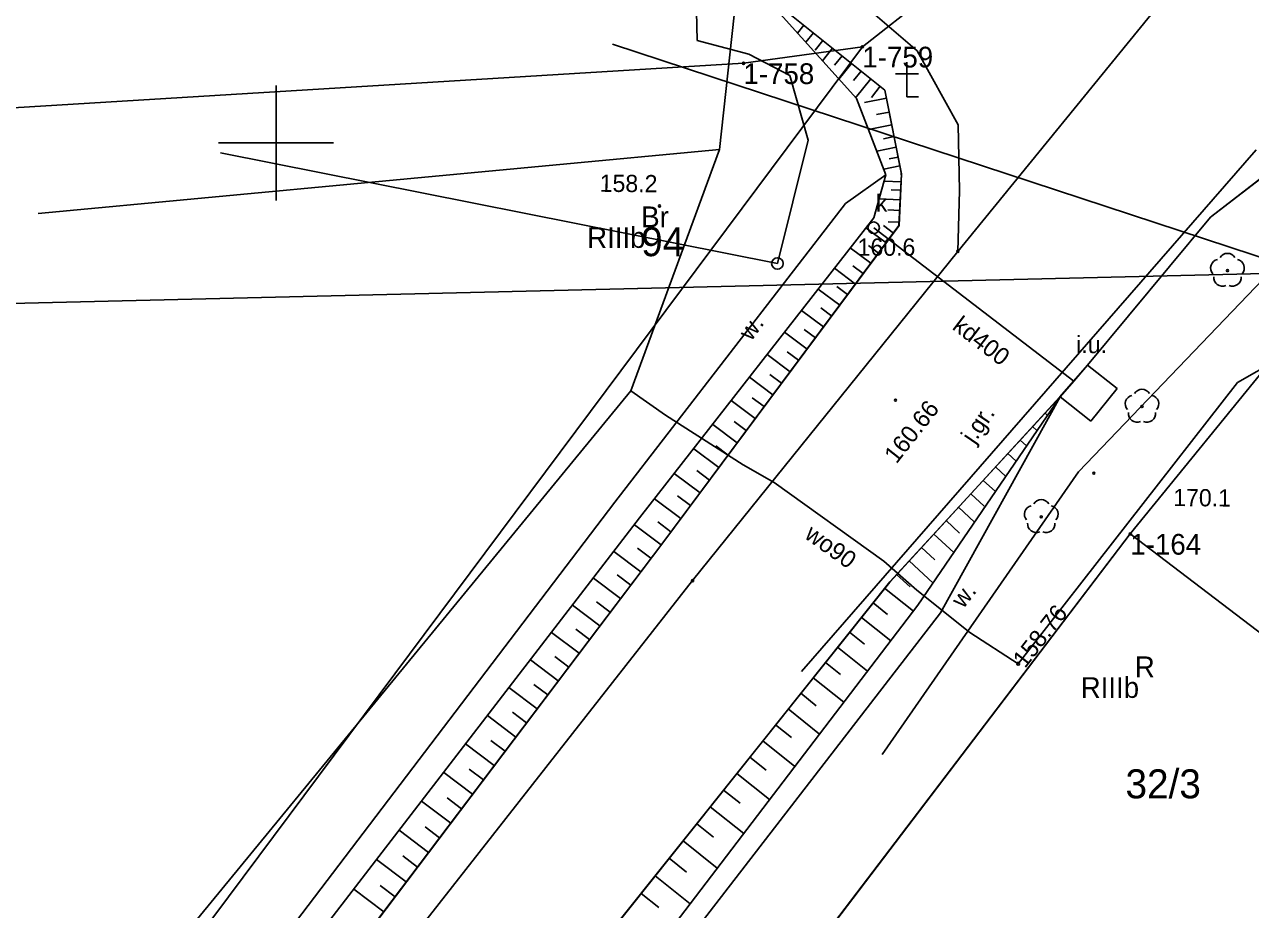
# Model space of a CAD drawing. Extents: x 5598798 to 5599616, y 5661498 to 5662453.
# Drawn here: x 5599039.1 to 5599092.4, y 5661566.7 to 5661605.1 of the extents above; entities that cross this region are included whole.
import ezdxf

# ---------------------------------------------------------------- set-up
doc = ezdxf.new("R2010")
doc.units = 0
for name, color, linetype in [('BUBZ_L_1', 7, 'Continuous'), ('Dzialki', 7, 'Continuous'), ('Kontury', 7, 'Continuous'), ('KTJZ_E_T_0', 7, 'Continuous'), ('KTJZ_L_0', 7, 'Continuous'), ('Numery_dzialek', 7, 'Continuous'), ('Numery_konturow', 7, 'Continuous'), ('Numery_punktow', 7, 'Continuous'), ('Numery_uzytkow', 7, 'Continuous'), ('OBOO_T_0', 7, 'Continuous'), ('OBOP_T_1', 7, 'Continuous'), ('Podzial_sekcyjny_krzyze', 7, 'Continuous'), ('PTRW_E_T_0', 7, 'Continuous'), ('PTRW_L_1', 7, 'Continuous'), ('Punkty', 7, 'Continuous'), ('RTPW_T_0', 7, 'Continuous'), ('RTPW_T_1', 7, 'Continuous'), ('SUOW_L_0', 7, 'Continuous'), ('SUPE_L_3', 7, 'Continuous'), ('SUPK_E_T_0', 7, 'Continuous'), ('SUPK_L_0', 7, 'Continuous'), ('SUPT_L_0', 7, 'Continuous'), ('SUPW_E_T_0', 7, 'Continuous'), ('SUPW_L_0', 7, 'Continuous'), ('SUSM_T_3', 7, 'Continuous'), ('SUTW_T_0', 7, 'Continuous'), ('SUUK_E_T_8', 7, 'Continuous'), ('SUUK_E_T_9', 7, 'Continuous'), ('SUUK_L_8', 7, 'Continuous'), ('SUUK_T_2', 7, 'Continuous'), ('Uzytki', 7, 'Continuous')]:
    doc.layers.add(name, color=color, linetype=linetype)

# ---------------------------------------------------------------- blocks, each defined once
blk = doc.blocks.new('GRO')
blk.add_circle((0, 0), 0.045)
blk = doc.blocks.new('2_OBOO01_01')
for p, q in [((0, 1.5), (0, 0)), ((-0.5, 1), (0.5, 1)), ((0, 0), (0.5, 0))]:
    blk.add_line(p, q)
blk = doc.blocks.new('2_OBOP02_01')
blk.add_circle((0, 0), 0.045)
for centre, start, end in [((0, 0.375056), 30.140124, 149.859876), ((-0.356659, 0.115892), 102.144465, 221.860023), ((0.356659, 0.115892), 318.139977, 77.855535), ((-0.220404, -0.303384), 174.148182, 293.854228), ((0.220404, -0.303384), 246.145772, 5.851818)]:
    blk.add_arc(centre, 0.375, start, end)
blk = doc.blocks.new('2_RTPW01')
blk.add_circle((0, 0), 0.045)
blk = doc.blocks.new('2_RTPW02')
blk.add_circle((0, 0), 0.045)
blk = doc.blocks.new('4_SUSM04_01')
blk.add_circle((0, 0), 0.25)
blk = doc.blocks.new('4_SUPS01_08')
blk.add_circle((0, 0), 0.0625)
blk = doc.blocks.new('4_SUUS15_05')
blk.add_circle((0, 0), 0.25)

msp = doc.modelspace()

# ---------------------------------------------------------------- linework, layer by layer
at = {"layer": 'BUBZ_L_1'}
for p, q in [((5599070.866619, 5661606.777722), (5599075.229063, 5661601.930102)), ((5599076.471074, 5661602.299748), (5599070.866619, 5661606.777722)), ((5599072.944885, 5661605.117182), (5599072.670266, 5661604.77348)), ((5599073.360538, 5661604.785074), (5599073.030995, 5661604.372631)), ((5599073.776191, 5661604.452966), (5599073.444083, 5661604.037313)), ((5599074.191844, 5661604.120859), (5599073.752454, 5661603.570934)), ((5599074.607497, 5661603.788751), (5599074.275389, 5661603.373097)), ((5599075.023151, 5661603.456643), (5599074.473912, 5661602.769238)), ((5599075.438804, 5661603.124535), (5599075.106696, 5661602.708881)), ((5599075.854457, 5661602.792427), (5599075.195371, 5661601.967541)), ((5599076.27011, 5661602.460319), (5599075.885608, 5661601.979091)), ((5599075.229063, 5661601.930102), (5599076.512086, 5661598.615971)), ((5599076.540369, 5661601.947766), (5599075.579508, 5661601.758599)), ((5599077.18899, 5661598.653147), (5599076.471074, 5661602.299748)), ((5599076.659354, 5661601.343395), (5599076.100379, 5661601.233348)), ((5599076.7694, 5661600.784421), (5599075.750273, 5661600.583782)), ((5599076.86972, 5661600.274857), (5599076.405199, 5661600.183406)), ((5599076.961171, 5661599.810336), (5599076.114252, 5661599.643601)), ((5599077.044539, 5661599.386877), (5599076.658511, 5661599.310878)), ((5599077.120537, 5661599.000849), (5599076.416727, 5661598.862288)), ((5599077.08532, 5661596.411278), (5599077.18899, 5661598.653147)), ((5599076.512086, 5661598.615971), (5599075.983367, 5661596.742132)), ((5599077.173142, 5661598.310425), (5599076.435498, 5661598.344535)), ((5599077.188792, 5661598.648868), (5599077.153389, 5661598.650505)), ((5599077.156086, 5661597.941603), (5599076.744319, 5661597.960644)), ((5599077.137045, 5661597.529836), (5599076.217621, 5661597.572353)), ((5599077.115787, 5661597.070124), (5599076.602546, 5661597.093857)), ((5599075.983367, 5661596.742132), (5599065.807304, 5661583.70311)), ((5599077.092053, 5661596.556883), (5599076.616602, 5661596.578869)), ((5599066.813154, 5661582.630911), (5599077.08532, 5661596.411278)), ((5599076.519789, 5661595.652604), (5599075.643087, 5661596.306116)), ((5599076.842968, 5661596.086157), (5599076.409415, 5661596.409336)), ((5599076.193033, 5661595.214254), (5599075.749831, 5661595.544626)), ((5599075.862661, 5661594.771051), (5599074.966447, 5661595.439108)), ((5599075.190908, 5661593.869877), (5599074.274746, 5661594.552803)), ((5599075.528633, 5661594.322944), (5599075.075566, 5661594.660669)), ((5599074.504203, 5661592.948646), (5599073.56765, 5661593.646771)), ((5599074.849445, 5661593.411796), (5599074.386294, 5661593.757038)), ((5599074.15514, 5661592.48037), (5599073.681682, 5661592.833295)), ((5599073.802215, 5661592.006911), (5599072.844817, 5661592.720574)), ((5599073.084602, 5661591.044215), (5599072.105896, 5661591.773763)), ((5599073.445383, 5661591.528212), (5599072.961386, 5661591.888993)), ((5599072.351017, 5661590.060093), (5599071.350528, 5661590.805878)), ((5599072.719828, 5661590.554862), (5599072.225059, 5661590.923673)), ((5599071.601105, 5661589.054068), (5599070.578348, 5661589.816452)), ((5599071.978125, 5661589.559849), (5599071.472344, 5661589.936868)), ((5599070.834503, 5661588.025651), (5599069.788982, 5661588.805003)), ((5599071.219913, 5661588.542689), (5599070.702875, 5661588.9281)), ((5599084.083213, 5661588.966374), (5599076.678362, 5661580.924495)), ((5599077.9025, 5661579.911014), (5599084.083213, 5661588.966374)), ((5599083.9679, 5661588.841141), (5599083.986221, 5661588.824271)), ((5599083.430397, 5661588.257398), (5599083.534117, 5661588.161894)), ((5599070.050838, 5661586.974345), (5599068.982047, 5661587.771043)), ((5599070.444826, 5661587.502891), (5599069.916281, 5661587.896879)), ((5599082.892895, 5661587.673654), (5599083.082013, 5661587.499517)), ((5599082.355392, 5661587.089911), (5599082.629909, 5661586.837139)), ((5599069.249731, 5661585.89964), (5599068.157152, 5661586.71407)), ((5599069.652488, 5661586.439949), (5599069.112179, 5661586.842707)), ((5599081.817889, 5661586.506168), (5599082.177805, 5661586.174762)), ((5599081.280386, 5661585.922424), (5599081.725701, 5661585.512385)), ((5599068.430793, 5661584.801015), (5599067.313897, 5661585.633572)), ((5599068.842515, 5661585.35335), (5599068.29018, 5661585.765072)), ((5599080.742884, 5661585.338681), (5599081.273597, 5661584.850007)), ((5599067.593629, 5661583.677938), (5599066.451874, 5661584.529026)), ((5599068.014515, 5661584.242567), (5599067.449886, 5661584.663452)), ((5599080.205381, 5661584.754938), (5599080.789124, 5661584.217435)), ((5599079.667878, 5661584.171194), (5599080.369389, 5661583.525253)), ((5599065.807304, 5661583.70311), (5599042.195012, 5661553.064547)), ((5599066.737121, 5661582.530399), (5599065.578805, 5661583.406618)), ((5599067.168085, 5661583.107061), (5599066.59089, 5661583.537314)), ((5599079.130375, 5661583.587451), (5599079.714119, 5661583.049948)), ((5599078.592872, 5661583.003708), (5599079.465181, 5661582.200498)), ((5599043.59456, 5661551.937133), (5599066.813154, 5661582.630911)), ((5599065.858935, 5661581.369484), (5599064.690196, 5661582.253587)), ((5599066.299011, 5661581.951242), (5599065.717254, 5661582.391318)), ((5599078.05537, 5661582.419964), (5599078.639113, 5661581.882462)), ((5599077.517867, 5661581.836221), (5599078.560973, 5661580.875743)), ((5599064.972847, 5661580.198121), (5599063.793591, 5661581.090181)), ((5599065.416884, 5661580.785114), (5599064.829891, 5661581.22915)), ((5599076.980364, 5661581.252478), (5599077.564108, 5661580.714975)), ((5599076.678362, 5661580.924495), (5599063.229428, 5661564.085129)), ((5599076.458557, 5661580.649278), (5599077.70574, 5661579.653203)), ((5599064.526818, 5661579.608493), (5599063.934543, 5661580.056525)), ((5599075.954972, 5661580.01874), (5599076.58551, 5661579.515154)), ((5599064.078786, 5661579.016218), (5599062.888918, 5661579.916305)), ((5599066.809784, 5661565.376446), (5599077.9025, 5661579.911014)), ((5599075.445776, 5661579.381178), (5599076.7209, 5661578.362787)), ((5599063.176679, 5661577.823679), (5599061.976103, 5661578.731866)), ((5599063.628742, 5661578.421284), (5599063.031137, 5661578.873348)), ((5599074.930908, 5661578.736513), (5599075.575573, 5661578.221646)), ((5599074.410305, 5661578.084668), (5599075.713996, 5661577.043461)), ((5599062.266454, 5661576.620409), (5599061.055074, 5661577.536768)), ((5599062.722585, 5661577.223392), (5599062.119603, 5661577.679523)), ((5599073.883902, 5661577.42556), (5599074.543009, 5661576.899157)), ((5599061.348038, 5661575.406311), (5599060.125758, 5661576.330916)), ((5599061.808274, 5661576.014719), (5599061.199865, 5661576.474956)), ((5599073.351635, 5661576.759111), (5599074.684534, 5661575.694577)), ((5599072.813438, 5661576.085237), (5599073.487312, 5661575.54704)), ((5599060.885735, 5661574.795171), (5599060.271851, 5661575.259549)), ((5599072.269247, 5661575.403856), (5599073.632008, 5661574.315472)), ((5599060.421357, 5661574.181287), (5599059.188078, 5661575.114213)), ((5599071.718993, 5661574.714885), (5599072.407964, 5661574.164631)), ((5599059.486338, 5661572.94524), (5599058.241961, 5661573.88656)), ((5599059.954894, 5661573.564648), (5599059.335487, 5661574.033204)), ((5599071.162609, 5661574.018238), (5599072.555901, 5661572.905471)), ((5599070.600027, 5661573.313832), (5599071.304434, 5661572.75125)), ((5599058.542904, 5661571.69807), (5599057.287329, 5661572.647861)), ((5599059.015677, 5661572.323051), (5599058.390696, 5661572.795824)), ((5599070.031178, 5661572.601578), (5599071.455686, 5661571.46388)), ((5599058.068008, 5661571.070282), (5599057.437403, 5661571.54731)), ((5599069.455992, 5661571.881389), (5599070.176181, 5661571.306204)), ((5599057.590981, 5661570.439676), (5599056.324107, 5661571.398015)), ((5599068.874399, 5661571.153178), (5599070.330821, 5661569.989992)), ((5599068.286327, 5661570.416855), (5599069.02265, 5661569.828783)), ((5599056.630491, 5661569.169959), (5599055.352218, 5661570.136921)), ((5599057.111812, 5661569.806239), (5599056.475531, 5661570.28756)), ((5599067.691704, 5661569.672329), (5599069.180755, 5661568.483083)), ((5599055.661359, 5661567.888816), (5599054.371582, 5661568.864479)), ((5599056.14701, 5661568.530822), (5599055.505004, 5661569.016474)), ((5599067.090456, 5661568.91951), (5599067.843276, 5661568.318262)), ((5599066.482511, 5661568.158304), (5599068.004923, 5661566.942414)), ((5599054.683505, 5661566.596144), (5599053.382122, 5661567.580587)), ((5599055.173527, 5661567.243927), (5599054.525743, 5661567.733949)), ((5599065.867794, 5661567.388618), (5599066.63748, 5661566.7739))]:
    msp.add_line(p, q, dxfattribs=at)
at = {"layer": 'Dzialki'}
for p, q in [((5599075.49, 5661604.18), (5599100.76, 5661624.05)), ((5599087.14, 5661583.01), (5599113.12, 5661614.97)), ((5599040.18, 5661556.86), (5599075.49, 5661604.18)), ((5599075.49, 5661604.18), (5599070.32, 5661603.46)), ((5599070.32, 5661603.46), (5599030.46, 5661601.04)), ((5599087.14, 5661583.01), (5599072.29, 5661563.53)), ((5599107.79, 5661567.29), (5599087.14, 5661583.01))]:
    msp.add_line(p, q, dxfattribs=at)
at = {"layer": 'Kontury'}
for p, q in [((5599075.49, 5661604.18), (5599040.18, 5661556.86)), ((5599070.32, 5661603.46), (5599075.49, 5661604.18)), ((5599030.46, 5661601.04), (5599070.32, 5661603.46)), ((5599087.14, 5661583.01), (5599045.53, 5661528.41)), ((5599127.28, 5661552.45), (5599087.14, 5661583.01))]:
    msp.add_line(p, q, dxfattribs=at)
at = {"layer": 'KTJZ_L_0'}
for p, q in [((5599090.42, 5661608.51), (5599079.64, 5661595.29)), ((5599070.87, 5661606.78), (5599076.47, 5661602.3)), ((5599077.87, 5661604.01), (5599074.48, 5661606.91)), ((5599079.66, 5661600.79), (5599077.87, 5661604.01)), ((5599076.47, 5661602.3), (5599077.19, 5661598.65)), ((5599079.71, 5661597.94), (5599079.66, 5661600.79)), ((5599072.84, 5661577.03), (5599092.61, 5661599.7)), ((5599090.63, 5661596.78), (5599093.18, 5661598.74)), ((5599077.19, 5661598.65), (5599077.08, 5661596.41)), ((5599079.64, 5661595.29), (5599079.71, 5661597.94)), ((5599085.28, 5661590.34), (5599090.63, 5661596.78)), ((5599077.08, 5661596.41), (5599066.81, 5661582.63)), ((5599079.64, 5661595.29), (5599068.11, 5661580.98)), ((5599084.08, 5661588.97), (5599085.28, 5661590.34)), ((5599076.68, 5661580.92), (5599084.08, 5661588.97)), ((5599066.81, 5661582.63), (5599043.59, 5661551.94)), ((5599068.11, 5661580.98), (5599036.03, 5661540.16)), ((5599063.23, 5661564.09), (5599076.68, 5661580.92))]:
    msp.add_line(p, q, dxfattribs=at)
at = {"layer": 'Podzial_sekcyjny_krzyze'}
for p, q in [((5599050, 5661597.5), (5599050, 5661602.5)), ((5599047.5, 5661600), (5599052.5, 5661600))]:
    msp.add_line(p, q, dxfattribs=at)
at = {"layer": 'PTRW_L_1'}
for p, q in [((5599090.626974, 5661596.782226), (5599093.183537, 5661598.743348)), ((5599074.75333, 5661597.367895), (5599076.512086, 5661598.615971)), ((5599076.512086, 5661598.615971), (5599075.983367, 5661596.742132)), ((5599064.730159, 5661584.391797), (5599074.75333, 5661597.367895)), ((5599075.983367, 5661596.742132), (5599065.807304, 5661583.70311)), ((5599090.626974, 5661596.782226), (5599085.282468, 5661590.344266)), ((5599094.36359, 5661595.600952), (5599084.881522, 5661585.712704)), ((5599085.282468, 5661590.344266), (5599084.083213, 5661588.966374)), ((5599084.083213, 5661588.966374), (5599078.884868, 5661579.576282)), ((5599084.881522, 5661585.712704), (5599076.349046, 5661573.424877)), ((5599041.326774, 5661553.647692), (5599064.730159, 5661584.391797)), ((5599065.807304, 5661583.70311), (5599042.195012, 5661553.064547)), ((5599060.855368, 5661556.243842), (5599078.884868, 5661579.576282))]:
    msp.add_line(p, q, dxfattribs=at)
at = {"layer": 'SUOW_L_0'}
msp.add_line((5599071.662016, 5661585.242449), (5599076.421794, 5661581.828971), dxfattribs=at)
msp.add_line((5599071.662016, 5661585.242449), (5599076.421794, 5661581.828971), dxfattribs=at)
at = {"layer": 'SUPE_L_3'}
for p, q in [((5599094.830509, 5661594.368063), (5599064.625935, 5661604.291571)), ((5598996.482621, 5661592.032784), (5599094.830509, 5661594.368063))]:
    msp.add_line(p, q, dxfattribs=at)
at = {"layer": 'SUPK_L_0'}
msp.add_line((5599075.98245, 5661596.315806), (5599084.68284, 5661589.65532), dxfattribs=at)
msp.add_line((5599075.98245, 5661596.315806), (5599084.68284, 5661589.65532), dxfattribs=at)
at = {"layer": 'SUPT_L_0'}
for p, q in [((5599068.113234, 5661613.285024), (5599068.303936, 5661604.455202)), ((5599068.303936, 5661604.455202), (5599070.5486, 5661603.855912)), ((5599070.5486, 5661603.855912), (5599072.330334, 5661602.935955)), ((5599072.330334, 5661602.935955), (5599073.134622, 5661600.122903)), ((5599073.134622, 5661600.122903), (5599071.795842, 5661594.759967)), ((5599071.795842, 5661594.759967), (5599047.577678, 5661599.576295))]:
    msp.add_line(p, q, dxfattribs=at)
at = {"layer": 'SUPW_L_0'}
for p, q in [((5599070.225874, 5661608.370705), (5599069.272086, 5661599.714965)), ((5599070.225874, 5661608.370705), (5599069.272086, 5661599.714965)), ((5599069.272086, 5661599.714965), (5599039.661276, 5661596.940988)), ((5599069.272086, 5661599.714965), (5599039.661276, 5661596.940988)), ((5599069.272086, 5661599.714965), (5599065.428445, 5661589.232718)), ((5599069.272086, 5661599.714965), (5599065.428445, 5661589.232718)), ((5599091.802605, 5661589.592031), (5599097.866615, 5661593.06142)), ((5599091.802605, 5661589.592031), (5599097.866615, 5661593.06142)), ((5599082.26584, 5661577.369633), (5599091.802605, 5661589.592031)), ((5599082.26584, 5661577.369633), (5599091.802605, 5661589.592031)), ((5599065.428445, 5661589.232718), (5599041.92742, 5661560.625386)), ((5599065.428445, 5661589.232718), (5599041.92742, 5661560.625386)), ((5599065.428445, 5661589.232718), (5599066.933375, 5661588.166403)), ((5599065.428445, 5661589.232718), (5599066.933375, 5661588.166403)), ((5599066.933375, 5661588.166403), (5599070.313898, 5661586.012186)), ((5599066.933375, 5661588.166403), (5599070.313898, 5661586.012186)), ((5599070.313898, 5661586.012186), (5599071.662016, 5661585.242449)), ((5599070.313898, 5661586.012186), (5599071.662016, 5661585.242449)), ((5599071.662016, 5661585.242449), (5599076.421794, 5661581.828971)), ((5599071.662016, 5661585.242449), (5599076.421794, 5661581.828971)), ((5599076.421794, 5661581.828971), (5599077.861045, 5661580.571075)), ((5599076.421794, 5661581.828971), (5599077.861045, 5661580.571075)), ((5599077.861045, 5661580.571075), (5599080.163893, 5661578.732524)), ((5599077.861045, 5661580.571075), (5599080.163893, 5661578.732524)), ((5599080.163893, 5661578.732524), (5599082.26584, 5661577.369633)), ((5599080.163893, 5661578.732524), (5599082.26584, 5661577.369633))]:
    msp.add_line(p, q, dxfattribs=at)
at = {"layer": 'SUUK_L_8'}
for p, q in [((5599084.68284, 5661589.65532), (5599085.282468, 5661590.344266)), ((5599085.282468, 5661590.344266), (5599086.566272, 5661589.32295)), ((5599084.083213, 5661588.966374), (5599084.68284, 5661589.65532)), ((5599086.566272, 5661589.32295), (5599085.417924, 5661587.906196)), ((5599085.417924, 5661587.906196), (5599084.083213, 5661588.966374))]:
    msp.add_line(p, q, dxfattribs=at)
at = {"layer": 'Uzytki'}
for p, q in [((5599040.18, 5661556.86), (5599075.49, 5661604.18)), ((5599075.49, 5661604.18), (5599070.32, 5661603.46)), ((5599070.32, 5661603.46), (5599030.46, 5661601.04)), ((5599087.14, 5661583.01), (5599045.53, 5661528.41)), ((5599127.28, 5661552.45), (5599087.14, 5661583.01))]:
    msp.add_line(p, q, dxfattribs=at)

# ---------------------------------------------------------------- block references
at = {"layer": 'OBOO_T_0'}
msp.add_blockref('2_OBOO01_01', (5599077.428203, 5661602.009631), dxfattribs=at)
at = {"layer": 'OBOP_T_1'}
for p in [(5599091.362851, 5661594.452407), (5599087.647309, 5661588.54735), (5599083.268278, 5661583.750321)]:
    msp.add_blockref('2_OBOP02_01', p, dxfattribs=at)
at = {"layer": 'Punkty'}
for p in [(5599075.49, 5661604.18), (5599070.32, 5661603.46), (5599087.14, 5661583.01)]:
    msp.add_blockref('GRO', p, dxfattribs=at)
at = {"layer": 'RTPW_T_0'}
for p in [(5599066.668217, 5661597.260824), (5599085.552113, 5661585.647856)]:
    msp.add_blockref('2_RTPW01', p, dxfattribs=at)
at = {"layer": 'RTPW_T_0', "rotation": -3.0000000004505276e-06}
for p in [(5599079.64, 5661595.29), (5599068.11, 5661580.98)]:
    msp.add_blockref('2_RTPW01', p, dxfattribs=at)
at = {"layer": 'RTPW_T_1'}
msp.add_blockref('2_RTPW02', (5599076.928918, 5661588.822993), dxfattribs=at)
at = {"layer": 'SUSM_T_3'}
msp.add_blockref('4_SUSM04_01', (5599071.795842, 5661594.759967), dxfattribs=at)
at = {"layer": 'SUTW_T_0'}
msp.add_blockref('4_SUPS01_08', (5599082.26584, 5661577.369633), dxfattribs=at)
at = {"layer": 'SUUK_T_2'}
msp.add_blockref('4_SUUS15_05', (5599075.98245, 5661596.315806), dxfattribs=at)

# ---------------------------------------------------------------- texts
at = {"layer": 'KTJZ_E_T_0'}
msp.add_text('j.gr.', height=0.75, rotation=55.900007, dxfattribs=at).set_placement((5599080.351392, 5661586.881284))
at = {"layer": 'Numery_dzialek'}
for s, p in [('94', (5599065.873691, 5661595.079716)), ('32/3', (5599086.92874, 5661571.52162))]:
    msp.add_text(s, height=1.26, dxfattribs=at).set_placement(p)
at = {"layer": 'Numery_konturow'}
for p in [(5599063.521451, 5661595.439716), (5599084.980093, 5661575.88623)]:
    msp.add_text('RIIIb', height=0.9, dxfattribs=at).set_placement(p)
at = {"layer": 'Numery_punktow'}
for s, p in [('1-759', (5599075.49, 5661603.28)), ('1-758', (5599070.32, 5661602.56)), ('1-164', (5599087.14, 5661582.11))]:
    msp.add_text(s, height=0.9, dxfattribs=at).set_placement(p)
at = {"layer": 'Numery_uzytkow'}
for s, p in [('Br', (5599065.873691, 5661596.339716)), ('R', (5599087.332332, 5661576.78623))]:
    msp.add_text(s, height=0.9, dxfattribs=at).set_placement(p)
at = {"layer": 'PTRW_E_T_0'}
for rotation, p in [(53.555558, (5599070.656551, 5661591.359573)), (52.02841, (5599079.877735, 5661579.732897))]:
    msp.add_text('w.', height=0.75, rotation=rotation, dxfattribs=at).set_placement(p)
at = {"layer": 'RTPW_T_0'}
for s, rotation, p in [('158.2', 359.464541, (5599064.066675, 5661597.878138)), ('170.1', 359.501788, (5599089.002258, 5661584.221353))]:
    msp.add_text(s, height=0.75, rotation=rotation, dxfattribs=at).set_placement(p)
msp.add_text('160.6', height=0.75, dxfattribs=at).set_placement((5599075.282983, 5661595.098409))
at = {"layer": 'RTPW_T_1'}
msp.add_text('160.66', height=0.75, rotation=51.766185, dxfattribs=at).set_placement((5599076.970386, 5661586.023896))
at = {"layer": 'SUPK_E_T_0'}
msp.add_text('kd400', height=0.75, rotation=322.564543, dxfattribs=at).set_placement((5599079.355435, 5661591.937451))
at = {"layer": 'SUPW_E_T_0'}
msp.add_text('wo90', height=0.75, rotation=324.353775, dxfattribs=at).set_placement((5599072.927392, 5661582.858086))
at = {"layer": 'SUTW_T_0'}
msp.add_text('158.76', height=0.75, rotation=52.036169, dxfattribs=at).set_placement((5599082.561489, 5661577.138946))
at = {"layer": 'SUUK_E_T_8'}
msp.add_text('i.u.', height=0.75, dxfattribs=at).set_placement((5599084.7891, 5661590.865538))
at = {"layer": 'SUUK_E_T_9'}
msp.add_text('k', height=0.75, dxfattribs=at).set_placement((5599076.079045, 5661597.008877))

doc.saveas('drawing.dxf')
